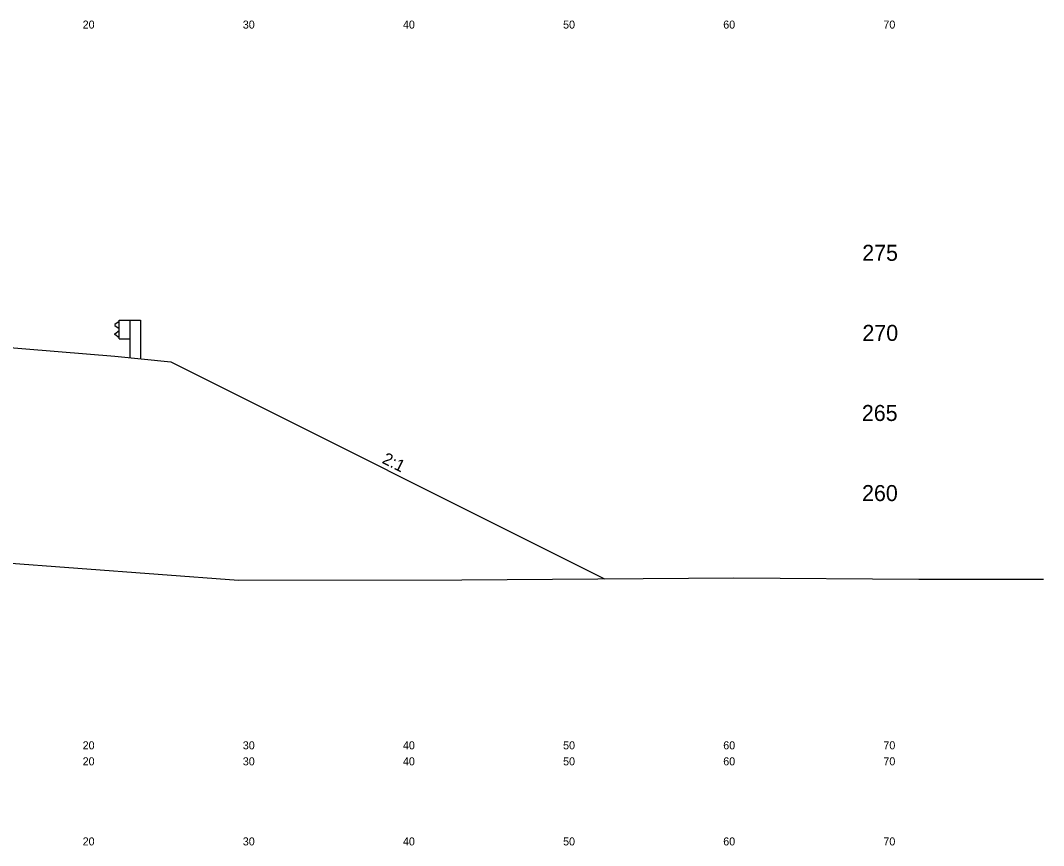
# Model space of a CAD drawing. Extents: x 1000 to 1162, y 999 to 8520.
# Drawn here: x 1096.1 to 1160, y 4328.5 to 4380 of the extents above; entities that cross this region are included whole.
import ezdxf

# ---------------------------------------------------------------- set-up
doc = ezdxf.new("R2010")
doc.units = 0
for name, color, linetype in [('Level 11', 7, 'Continuous'), ('Level 24', 7, 'Continuous'), ('Level 32', 7, 'Continuous'), ('Level 56', 7, 'Continuous'), ('Level 6', 7, 'Continuous'), ('Level 60', 7, 'Continuous'), ('Level 7', 7, 'Continuous')]:
    doc.layers.add(name, color=color, linetype=linetype)

msp = doc.modelspace()

# ---------------------------------------------------------------- linework, layer by layer
at = {"layer": 'Level 24'}
for p, q in [((1102.271, 4361.219), (1102, 4361.019)), ((1102, 4361.019), (1102, 4360.969)), ((1102, 4360.969), (1102.271, 4360.769)), ((1102.271, 4360.125), (1102.271, 4361.292)), ((1102.271, 4361.292), (1102.937, 4361.292)), ((1102.937, 4361.292), (1102.937, 4358.949)), ((1102.937, 4361.292), (1103.603, 4361.292)), ((1103.603, 4361.292), (1103.603, 4358.882)), ((1102, 4360.448), (1102.271, 4360.648)), ((1102, 4360.398), (1102, 4360.448)), ((1102.271, 4360.198), (1102, 4360.398)), ((1102.271, 4360.125), (1102.938, 4360.125))]:
    msp.add_line(p, q, dxfattribs=at)
at = {"layer": 'Level 6'}
for p, q in [((1094, 4359.709), (1102, 4359.042)), ((1102, 4359.042), (1105.5, 4358.692))]:
    msp.add_line(p, q, dxfattribs=at)
at = {"layer": 'Level 60'}
for p, q in [((1083.079, 4347.064), (1109.721, 4345.056)), ((1109.721, 4345.056), (1123.681, 4345.092)), ((1123.681, 4345.092), (1140.667, 4345.212)), ((1140.667, 4345.212), (1152.219, 4345.133)), ((1152.219, 4345.133), (1160, 4345.133))]:
    msp.add_line(p, q, dxfattribs=at)
at = {"layer": 'Level 7'}
msp.add_line((1105.5, 4358.692), (1132.575, 4345.155), dxfattribs=at)

# ---------------------------------------------------------------- texts
at = {"layer": 'Level 11'}
for s, p in [(' 275', (1148.307, 4365)), (' 270', (1148.319, 4360)), (' 265', (1148.284, 4355)), (' 260', (1148.295, 4350))]:
    msp.add_text(s, height=1, dxfattribs=at).set_placement(p)
at = {"layer": 'Level 32'}
msp.add_text('2:1', height=0.75, rotation=333.43495, dxfattribs=at).set_placement((1118.642, 4352.4))
at = {"layer": 'Level 56'}
for s, p in [('20', (1100, 4379.5)), ('30', (1110, 4379.5)), ('40', (1120, 4379.5)), ('50', (1130, 4379.5)), ('60', (1140, 4379.5)), ('70', (1150, 4379.5)), ('20', (1100, 4334.5)), ('30', (1110, 4334.5)), ('40', (1120, 4334.5)), ('50', (1130, 4334.5)), ('60', (1140, 4334.5)), ('70', (1150, 4334.5)), ('20', (1100, 4333.5)), ('30', (1110, 4333.5)), ('40', (1120, 4333.5)), ('50', (1130, 4333.5)), ('60', (1140, 4333.5)), ('70', (1150, 4333.5)), ('20', (1100, 4328.5)), ('30', (1110, 4328.5)), ('40', (1120, 4328.5)), ('50', (1130, 4328.5)), ('60', (1140, 4328.5)), ('70', (1150, 4328.5))]:
    msp.add_text(s, height=0.5, dxfattribs=at).set_placement(p)

doc.saveas('drawing.dxf')
